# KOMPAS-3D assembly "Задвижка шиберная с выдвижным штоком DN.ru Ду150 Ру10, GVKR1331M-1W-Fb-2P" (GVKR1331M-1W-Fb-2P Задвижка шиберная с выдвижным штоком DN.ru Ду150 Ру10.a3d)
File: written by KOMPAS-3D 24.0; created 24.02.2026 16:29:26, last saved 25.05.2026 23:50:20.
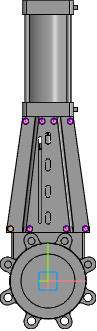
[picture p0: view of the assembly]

Document properties: Автор: R2D2; Полное имя файла: E:\Работа\Зайцев\GVKR1331M-1W-Fb-2P Задвижка шиберная с выдвижным штоком DN.ru Ду50-300 Ру16-10-6 с пневмоприводом\исходные материалы\DN150\GVKR1331M-1W-Fb-2P Задвижка шиберная с выдвижным штоком DN.ru Ду150 Ру10.a3d

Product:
- Component [detail]: Затвор дисковый DN.ru Ду Ру  | qty 1  | pos. 1  | Масса: 18.2; Раздел спецификации: Прочие изделия; Примечание: D050-23732; Автор: R2D2; source file: Задвижка шиберная РЕЗЬБОВОЙ DN.ru Ду Ру.m3d
- Component [detail]: Пневмоцилиндр  | qty 1  | pos. 2  | Масса: 39.90479; Автор: R2D2; source file: Пневмоцилиндр.m3d
- Component [standard]: Hexagon head screw ISO 4017 - М10 x 25  | qty 8  | pos. 5  | Масса: 0.026096; Раздел спецификации: Стандартные изделия; Рассекать на разрезах: no
- Component [detail]: лист  | qty 2  | pos. 3  | Масса: 2.142327; Раздел спецификации: Прочие изделия; Примечание: D040-08800; Автор: R2D2; source file: лист.m3d
- Component [detail]: шибер  | qty 1  | pos. 4  | Масса: 2.222585; Раздел спецификации: Прочие изделия; Примечание: D040-08800; Автор: R2D2; source file: шибер.m3d
- Component [standard]: Hexagon head screw ISO 4017 - М8 x 16  | qty 8  | Масса: 0.012085; Раздел спецификации: Стандартные изделия; Рассекать на разрезах: no
- Part/product: Задвижка шиберная с выдвижным штоком DN.ru Ду150 Ру10  | designation GVKR1331M-1W-Fb-2P
    Масса: 23
    Раздел спецификации: Прочие изделия
    Примечание: D040-08796

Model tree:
1. Точка:1  (with: Ребро.Отверстие в листовом теле:2)
     X = -50.6312; Y = 145; Z = 59
2. Точка:2  (with: Ребро.Отверстие в листовом теле:3)
     X = 50.6312; Y = 145; Z = 59
3. Точка:3  (with: Ребро.Отверстие в листовом теле:4)
     X = 103.983; Y = 145; Z = 34
4. Точка:4  (with: Ребро.Отверстие в листовом теле:5)
     X = -61.6718; Y = 443.5; Z = 34
5. Точка:5  (with: Ребро.Отверстие в листовом теле:6)
     X = -16.3374; Y = 443.5; Z = 59
6. Точка:6  (with: Ребро.Отверстие в листовом теле:7)
     X = 16.3374; Y = 443.5; Z = 59
7. Точка:7  (with: Ребро.Отверстие в листовом теле:8)
     X = 61.6718; Y = 443.5; Z = 34
8. Массив по точкам:1
9. Экземпляр ( 6 )
10. Экземпляр ( 4 )
11. Экземпляр ( 1 )
12. Экземпляр ( 7 )
13. Экземпляр ( 3 )
14. Экземпляр ( 5 )
15. Экземпляр ( 2 )
16. Контекстная связь:1  (with: Эскиз:7, Грань.Элемент выдавливания:6, Ребро.Элемент выдавливания:6, Ребро.Элемент выдавливания:12, Контекстная связь (лист (1)):1)
17. Контекстная связь:2  (with: Эскиз:6, Грань.Элемент выдавливания:15, Ребро.Элемент выдавливания:15, Контекстная связь (лист (1)):2)
18. Контекстная связь:3  (with: Эскиз:5, Грань.Элемент выдавливания:1, Вершина.Элемент выдавливания:15, Контекстная связь (шибер):3, Грань.Элемент выдавливания:8, Грань.Линейчатая обечайка:1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)
     Ориентация = 2; Ориентация = 2; Ориентация = 2; Ориентация = 2; Ориентация = 2; Ориентация = 2; Ориентация = 2; Ориентация = 2; Ориентация = 2

Expressions: D050-23732; D040-08800
Referenced files in E:\Работа\Зайцев\GVKR1331M-1W-Fb-2P Задвижка шиберная с выдвижным штоком DN.ru Ду50-300 Ру16-10-6 с пневмоприводом\исходные материалы\DN150\: Задвижка шиберная РЕЗЬБОВОЙ DN.ru Ду Ру.m3d, Пневмоцилиндр.m3d, лист.m3d, шибер.m3d
Referenced files in C:\Program Files\ASCON\KOMPAS-3D v24\Libs\PolynomLib\DATA\vault\Methods\Kompas\3D\: PLib_Bolt_1_ISO_1100.m3d
Referenced files in E:\Работа\Зайцев\GVKR1331E-1W-Fb-2P Задвижка шиберная DN.ru Ду50-300 Ру16-10-6\исходные материалы\DN80\: лист.m3d
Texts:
  Hexagon head screw
  BOSimple***PART:f114febc-ab7b-6638-bb5e-15f0e2e47160***SHORTLOC:A259_7B16EF33AB1642D2[16;1,5;25;10;-;Undefined]
  BOSimple***PART:17775d1c-e7de-f283-40f0-d40789f7f59e***SHORTLOC:A259_7B16EF33AB1642D2[13;1,25;16;8;-;Undefined]
  Программные изделия  и базы данных
  GVKR1331M-1W-Fb-2P
  Hexagon head screw ISO 4017 - М10 x 25 (1)
  hole1
  hole2
  лист (1)
  Hexagon head screw ISO 4017 - М10 x 25 (2)
  Hexagon head screw ISO 4017 - М10 x 25 (3)
  Hexagon head screw ISO 4017 - М10 x 25 (4)
  Hexagon head screw ISO 4017 - М10 x 25 (5)
  Hexagon head screw ISO 4017 - М10 x 25 (6)
  Hexagon head screw ISO 4017 - М10 x 25 (7)
  Hexagon head screw ISO 4017 - М10 x 25 (8)
  лист (2)
  Hexagon head screw ISO 4017 - М8 x 16 (1)
  Hexagon head screw ISO 4017 - М8 x 16 (2)
  Hexagon head screw ISO 4017 - М8 x 16 (3)
  Hexagon head screw ISO 4017 - М8 x 16 (4)
  Hexagon head screw ISO 4017 - М8 x 16 (5)
  Hexagon head screw ISO 4017 - М8 x 16 (6)
  Hexagon head screw ISO 4017 - М8 x 16 (7)
  Hexagon head screw ISO 4017 - М8 x 16 (8)
  Ось Y.Начало координат
  Плоскость ZY.Начало координат
  Плоскость ZX.Начало координат
  Плоскость XY.Начало координат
